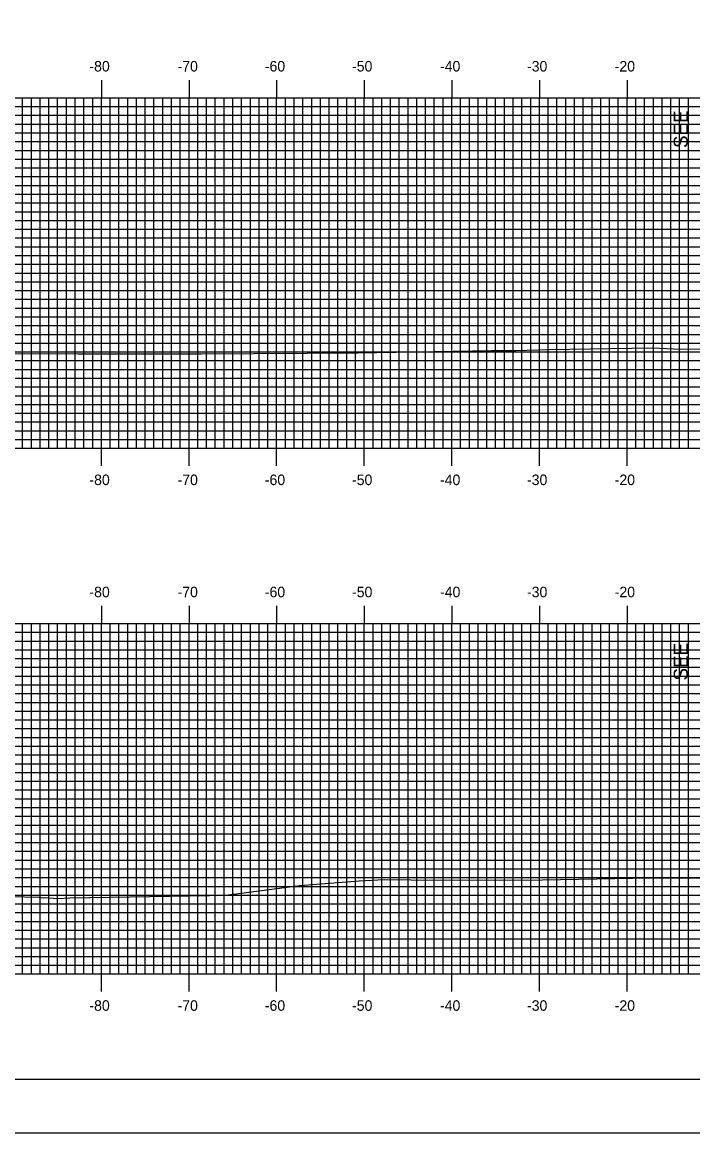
# Model space of a CAD drawing. Extents: x 2846 to 3190, y -1658 to -1438.
# Drawn here: x 2923.2 to 2999.7, y -1657.7 to -1531 of the extents above; entities that cross this region are included whole.
import ezdxf

# ---------------------------------------------------------------- set-up
doc = ezdxf.new("R2010")
doc.units = 0
for name, color, linetype in [('ANNOTATION', 7, 'Continuous'), ('BORDER', 7, 'Continuous'), ('H_V ANNOTATION', 7, 'Continuous'), ('MAJOR', 7, 'Continuous'), ('MINOR', 7, 'Continuous'), ('PLOT BOUNDARY', 7, 'Continuous'), ('S_Roadway_Centerline', 7, 'Continuous')]:
    doc.layers.add(name, color=color, linetype=linetype)

msp = doc.modelspace()

# ---------------------------------------------------------------- linework, layer by layer
at = {"layer": 'BORDER'}
msp.add_lwpolyline([(2862.61, -1651.6), (3182.61, -1651.6), (3182.61, -1441.6), (2862.61, -1441.6)], close=True, dxfattribs=at)
at = {"layer": 'MAJOR'}
for p, q in [((2932.21, -1537.6), (2932.21, -1539.6)), ((2942.21, -1537.6), (2942.21, -1539.6)), ((2952.21, -1537.6), (2952.21, -1539.6)), ((2962.21, -1537.6), (2962.21, -1539.6)), ((2972.21, -1537.6), (2972.21, -1539.6)), ((2982.21, -1537.6), (2982.21, -1539.6)), ((2992.21, -1537.6), (2992.21, -1539.6)), ((2872.21, -1539.6), (3152.21, -1539.6)), ((2872.21, -1539.6), (3152.21, -1539.6)), ((2932.21, -1579.6), (2932.21, -1539.6)), ((2942.21, -1579.6), (2942.21, -1539.6)), ((2952.21, -1579.6), (2952.21, -1539.6)), ((2962.21, -1579.6), (2962.21, -1539.6)), ((2972.21, -1579.6), (2972.21, -1539.6)), ((2982.21, -1579.6), (2982.21, -1539.6)), ((2992.21, -1579.6), (2992.21, -1539.6)), ((2872.21, -1544.6), (3152.21, -1544.6)), ((2872.21, -1549.6), (3152.21, -1549.6)), ((2872.21, -1554.6), (3152.21, -1554.6)), ((2872.21, -1559.6), (3152.21, -1559.6)), ((2872.21, -1564.6), (3152.21, -1564.6)), ((2872.21, -1569.6), (3152.21, -1569.6)), ((2872.21, -1574.6), (3152.21, -1574.6)), ((2872.21, -1579.6), (3152.21, -1579.6)), ((2872.21, -1579.6), (3152.21, -1579.6)), ((2932.21, -1581.61), (2932.21, -1579.6)), ((2942.21, -1581.61), (2942.21, -1579.6)), ((2952.21, -1581.61), (2952.21, -1579.6)), ((2962.21, -1581.61), (2962.21, -1579.6)), ((2972.21, -1581.61), (2972.21, -1579.6)), ((2982.21, -1581.61), (2982.21, -1579.6)), ((2992.21, -1581.61), (2992.21, -1579.6)), ((2932.21, -1597.6), (2932.21, -1599.6)), ((2942.21, -1597.6), (2942.21, -1599.6)), ((2952.21, -1597.6), (2952.21, -1599.6)), ((2962.21, -1597.6), (2962.21, -1599.6)), ((2972.21, -1597.6), (2972.21, -1599.6)), ((2982.21, -1597.6), (2982.21, -1599.6)), ((2992.21, -1597.6), (2992.21, -1599.6)), ((2872.21, -1599.6), (3152.21, -1599.6)), ((2872.21, -1599.6), (3152.21, -1599.6)), ((2932.21, -1639.6), (2932.21, -1599.6)), ((2942.21, -1639.6), (2942.21, -1599.6)), ((2952.21, -1639.6), (2952.21, -1599.6)), ((2962.21, -1639.6), (2962.21, -1599.6)), ((2972.21, -1639.6), (2972.21, -1599.6)), ((2982.21, -1639.6), (2982.21, -1599.6)), ((2992.21, -1639.6), (2992.21, -1599.6)), ((2872.21, -1604.6), (3152.21, -1604.6)), ((2872.21, -1609.6), (3152.21, -1609.6)), ((2872.21, -1614.6), (3152.21, -1614.6)), ((2872.21, -1619.6), (3152.21, -1619.6)), ((2872.21, -1624.6), (3152.21, -1624.6)), ((2872.21, -1629.6), (3152.21, -1629.6)), ((2872.21, -1634.6), (3152.21, -1634.6)), ((2872.21, -1639.6), (3152.21, -1639.6)), ((2872.21, -1639.6), (3152.21, -1639.6)), ((2932.21, -1641.61), (2932.21, -1639.6)), ((2942.21, -1641.61), (2942.21, -1639.6)), ((2952.21, -1641.61), (2952.21, -1639.6)), ((2962.21, -1641.61), (2962.21, -1639.6)), ((2972.21, -1641.61), (2972.21, -1639.6)), ((2982.21, -1641.61), (2982.21, -1639.6)), ((2992.21, -1641.61), (2992.21, -1639.6))]:
    msp.add_line(p, q, dxfattribs=at)
at = {"layer": 'MINOR'}
for p, q in [((2923.21, -1579.6), (2923.21, -1539.6)), ((2924.21, -1579.6), (2924.21, -1539.6)), ((2925.21, -1579.6), (2925.21, -1539.6)), ((2926.21, -1579.6), (2926.21, -1539.6)), ((2927.21, -1579.6), (2927.21, -1539.6)), ((2928.21, -1579.6), (2928.21, -1539.6)), ((2929.21, -1579.6), (2929.21, -1539.6)), ((2930.21, -1579.6), (2930.21, -1539.6)), ((2931.21, -1579.6), (2931.21, -1539.6)), ((2933.21, -1579.6), (2933.21, -1539.6)), ((2934.21, -1579.6), (2934.21, -1539.6)), ((2935.21, -1579.6), (2935.21, -1539.6)), ((2936.21, -1579.6), (2936.21, -1539.6)), ((2937.21, -1579.6), (2937.21, -1539.6)), ((2938.21, -1579.6), (2938.21, -1539.6)), ((2939.21, -1579.6), (2939.21, -1539.6)), ((2940.21, -1579.6), (2940.21, -1539.6)), ((2941.21, -1579.6), (2941.21, -1539.6)), ((2943.21, -1579.6), (2943.21, -1539.6)), ((2944.21, -1579.6), (2944.21, -1539.6)), ((2945.21, -1579.6), (2945.21, -1539.6)), ((2946.21, -1579.6), (2946.21, -1539.6)), ((2947.21, -1579.6), (2947.21, -1539.6)), ((2948.21, -1579.6), (2948.21, -1539.6)), ((2949.21, -1579.6), (2949.21, -1539.6)), ((2950.21, -1579.6), (2950.21, -1539.6)), ((2951.21, -1579.6), (2951.21, -1539.6)), ((2953.21, -1579.6), (2953.21, -1539.6)), ((2954.21, -1579.6), (2954.21, -1539.6)), ((2955.21, -1579.6), (2955.21, -1539.6)), ((2956.21, -1579.6), (2956.21, -1539.6)), ((2957.21, -1579.6), (2957.21, -1539.6)), ((2958.21, -1579.6), (2958.21, -1539.6)), ((2959.21, -1579.6), (2959.21, -1539.6)), ((2960.21, -1579.6), (2960.21, -1539.6)), ((2961.21, -1579.6), (2961.21, -1539.6)), ((2963.21, -1579.6), (2963.21, -1539.6)), ((2964.21, -1579.6), (2964.21, -1539.6)), ((2965.21, -1579.6), (2965.21, -1539.6)), ((2966.21, -1579.6), (2966.21, -1539.6)), ((2967.21, -1579.6), (2967.21, -1539.6)), ((2968.21, -1579.6), (2968.21, -1539.6)), ((2969.21, -1579.6), (2969.21, -1539.6)), ((2970.21, -1579.6), (2970.21, -1539.6)), ((2971.21, -1579.6), (2971.21, -1539.6)), ((2973.21, -1579.6), (2973.21, -1539.6)), ((2974.21, -1579.6), (2974.21, -1539.6)), ((2975.21, -1579.6), (2975.21, -1539.6)), ((2976.21, -1579.6), (2976.21, -1539.6)), ((2977.21, -1579.6), (2977.21, -1539.6)), ((2978.21, -1579.6), (2978.21, -1539.6)), ((2979.21, -1579.6), (2979.21, -1539.6)), ((2980.21, -1579.6), (2980.21, -1539.6)), ((2981.21, -1579.6), (2981.21, -1539.6)), ((2983.21, -1579.6), (2983.21, -1539.6)), ((2984.21, -1579.6), (2984.21, -1539.6)), ((2985.21, -1579.6), (2985.21, -1539.6)), ((2986.21, -1579.6), (2986.21, -1539.6)), ((2987.21, -1579.6), (2987.21, -1539.6)), ((2988.21, -1579.6), (2988.21, -1539.6)), ((2989.21, -1579.6), (2989.21, -1539.6)), ((2990.21, -1579.6), (2990.21, -1539.6)), ((2991.21, -1579.6), (2991.21, -1539.6)), ((2993.21, -1579.6), (2993.21, -1539.6)), ((2994.21, -1579.6), (2994.21, -1539.6)), ((2995.21, -1579.6), (2995.21, -1539.6)), ((2996.21, -1579.6), (2996.21, -1539.6)), ((2997.21, -1579.6), (2997.21, -1539.6)), ((2998.21, -1579.6), (2998.21, -1539.6)), ((2999.21, -1579.6), (2999.21, -1539.6)), ((2872.21, -1540.6), (3152.21, -1540.6)), ((2872.21, -1541.6), (3152.21, -1541.6)), ((2872.21, -1542.6), (3152.21, -1542.6)), ((2872.21, -1543.6), (3152.21, -1543.6)), ((2872.21, -1545.6), (3152.21, -1545.6)), ((2872.21, -1546.6), (3152.21, -1546.6)), ((2872.21, -1547.6), (3152.21, -1547.6)), ((2872.21, -1548.6), (3152.21, -1548.6)), ((2872.21, -1550.6), (3152.21, -1550.6)), ((2872.21, -1551.6), (3152.21, -1551.6)), ((2872.21, -1552.6), (3152.21, -1552.6)), ((2872.21, -1553.6), (3152.21, -1553.6)), ((2872.21, -1555.6), (3152.21, -1555.6)), ((2872.21, -1556.6), (3152.21, -1556.6)), ((2872.21, -1557.6), (3152.21, -1557.6)), ((2872.21, -1558.6), (3152.21, -1558.6)), ((2872.21, -1560.6), (3152.21, -1560.6)), ((2872.21, -1561.6), (3152.21, -1561.6)), ((2872.21, -1562.6), (3152.21, -1562.6)), ((2872.21, -1563.6), (3152.21, -1563.6)), ((2872.21, -1565.6), (3152.21, -1565.6)), ((2872.21, -1566.6), (3152.21, -1566.6)), ((2872.21, -1567.6), (3152.21, -1567.6)), ((2872.21, -1568.6), (3152.21, -1568.6)), ((2872.21, -1570.6), (3152.21, -1570.6)), ((2872.21, -1571.6), (3152.21, -1571.6)), ((2872.21, -1572.6), (3152.21, -1572.6)), ((2872.21, -1573.6), (3152.21, -1573.6)), ((2872.21, -1575.6), (3152.21, -1575.6)), ((2872.21, -1576.6), (3152.21, -1576.6)), ((2872.21, -1577.6), (3152.21, -1577.6)), ((2872.21, -1578.6), (3152.21, -1578.6)), ((2872.21, -1600.6), (3152.21, -1600.6)), ((2923.21, -1639.6), (2923.21, -1599.6)), ((2924.21, -1639.6), (2924.21, -1599.6)), ((2925.21, -1639.6), (2925.21, -1599.6)), ((2926.21, -1639.6), (2926.21, -1599.6)), ((2927.21, -1639.6), (2927.21, -1599.6)), ((2928.21, -1639.6), (2928.21, -1599.6)), ((2929.21, -1639.6), (2929.21, -1599.6)), ((2930.21, -1639.6), (2930.21, -1599.6)), ((2931.21, -1639.6), (2931.21, -1599.6)), ((2933.21, -1639.6), (2933.21, -1599.6)), ((2934.21, -1639.6), (2934.21, -1599.6)), ((2935.21, -1639.6), (2935.21, -1599.6)), ((2936.21, -1639.6), (2936.21, -1599.6)), ((2937.21, -1639.6), (2937.21, -1599.6)), ((2938.21, -1639.6), (2938.21, -1599.6)), ((2939.21, -1639.6), (2939.21, -1599.6)), ((2940.21, -1639.6), (2940.21, -1599.6)), ((2941.21, -1639.6), (2941.21, -1599.6)), ((2943.21, -1639.6), (2943.21, -1599.6)), ((2944.21, -1639.6), (2944.21, -1599.6)), ((2945.21, -1639.6), (2945.21, -1599.6)), ((2946.21, -1639.6), (2946.21, -1599.6)), ((2947.21, -1639.6), (2947.21, -1599.6)), ((2948.21, -1639.6), (2948.21, -1599.6)), ((2949.21, -1639.6), (2949.21, -1599.6)), ((2950.21, -1639.6), (2950.21, -1599.6)), ((2951.21, -1639.6), (2951.21, -1599.6)), ((2953.21, -1639.6), (2953.21, -1599.6)), ((2954.21, -1639.6), (2954.21, -1599.6)), ((2955.21, -1639.6), (2955.21, -1599.6)), ((2956.21, -1639.6), (2956.21, -1599.6)), ((2957.21, -1639.6), (2957.21, -1599.6)), ((2958.21, -1639.6), (2958.21, -1599.6)), ((2959.21, -1639.6), (2959.21, -1599.6)), ((2960.21, -1639.6), (2960.21, -1599.6)), ((2961.21, -1639.6), (2961.21, -1599.6)), ((2963.21, -1639.6), (2963.21, -1599.6)), ((2964.21, -1639.6), (2964.21, -1599.6)), ((2965.21, -1639.6), (2965.21, -1599.6)), ((2966.21, -1639.6), (2966.21, -1599.6)), ((2967.21, -1639.6), (2967.21, -1599.6)), ((2968.21, -1639.6), (2968.21, -1599.6)), ((2969.21, -1639.6), (2969.21, -1599.6)), ((2970.21, -1639.6), (2970.21, -1599.6)), ((2971.21, -1639.6), (2971.21, -1599.6)), ((2973.21, -1639.6), (2973.21, -1599.6)), ((2974.21, -1639.6), (2974.21, -1599.6)), ((2975.21, -1639.6), (2975.21, -1599.6)), ((2976.21, -1639.6), (2976.21, -1599.6)), ((2977.21, -1639.6), (2977.21, -1599.6)), ((2978.21, -1639.6), (2978.21, -1599.6)), ((2979.21, -1639.6), (2979.21, -1599.6)), ((2980.21, -1639.6), (2980.21, -1599.6)), ((2981.21, -1639.6), (2981.21, -1599.6)), ((2983.21, -1639.6), (2983.21, -1599.6)), ((2984.21, -1639.6), (2984.21, -1599.6)), ((2985.21, -1639.6), (2985.21, -1599.6)), ((2986.21, -1639.6), (2986.21, -1599.6)), ((2987.21, -1639.6), (2987.21, -1599.6)), ((2988.21, -1639.6), (2988.21, -1599.6)), ((2989.21, -1639.6), (2989.21, -1599.6)), ((2990.21, -1639.6), (2990.21, -1599.6)), ((2991.21, -1639.6), (2991.21, -1599.6)), ((2993.21, -1639.6), (2993.21, -1599.6)), ((2994.21, -1639.6), (2994.21, -1599.6)), ((2995.21, -1639.6), (2995.21, -1599.6)), ((2996.21, -1639.6), (2996.21, -1599.6)), ((2997.21, -1639.6), (2997.21, -1599.6)), ((2998.21, -1639.6), (2998.21, -1599.6)), ((2999.21, -1639.6), (2999.21, -1599.6)), ((2872.21, -1601.6), (3152.21, -1601.6)), ((2872.21, -1602.6), (3152.21, -1602.6)), ((2872.21, -1603.6), (3152.21, -1603.6)), ((2872.21, -1605.6), (3152.21, -1605.6)), ((2872.21, -1606.6), (3152.21, -1606.6)), ((2872.21, -1607.6), (3152.21, -1607.6)), ((2872.21, -1608.6), (3152.21, -1608.6)), ((2872.21, -1610.6), (3152.21, -1610.6)), ((2872.21, -1611.6), (3152.21, -1611.6)), ((2872.21, -1612.6), (3152.21, -1612.6)), ((2872.21, -1613.6), (3152.21, -1613.6)), ((2872.21, -1615.6), (3152.21, -1615.6)), ((2872.21, -1616.6), (3152.21, -1616.6)), ((2872.21, -1617.6), (3152.21, -1617.6)), ((2872.21, -1618.6), (3152.21, -1618.6)), ((2872.21, -1620.6), (3152.21, -1620.6)), ((2872.21, -1621.6), (3152.21, -1621.6)), ((2872.21, -1622.6), (3152.21, -1622.6)), ((2872.21, -1623.6), (3152.21, -1623.6)), ((2872.21, -1625.6), (3152.21, -1625.6)), ((2872.21, -1626.6), (3152.21, -1626.6)), ((2872.21, -1627.6), (3152.21, -1627.6)), ((2872.21, -1628.6), (3152.21, -1628.6)), ((2872.21, -1630.6), (3152.21, -1630.6)), ((2872.21, -1631.6), (3152.21, -1631.6)), ((2872.21, -1632.6), (3152.21, -1632.6)), ((2872.21, -1633.6), (3152.21, -1633.6)), ((2872.21, -1635.6), (3152.21, -1635.6)), ((2872.21, -1636.6), (3152.21, -1636.6)), ((2872.21, -1637.6), (3152.21, -1637.6)), ((2872.21, -1638.6), (3152.21, -1638.6))]:
    msp.add_line(p, q, dxfattribs=at)
at = {"layer": 'PLOT BOUNDARY'}
msp.add_lwpolyline([(2846.43, -1657.72), (3186.43, -1657.72), (3186.43, -1437.72), (2846.43, -1437.72)], close=True, dxfattribs=at)
at = {"layer": 'S_Roadway_Centerline'}
for points in [[(2872.21, -1568.96), (2876.43, -1569.03), (2887.71, -1568.78), (2892.45, -1569.04), (2907.03, -1568.85), (2913.06, -1568.81), (2923.46, -1568.8), (2929.56, -1568.81), (2943.58, -1568.84), (2955.7, -1568.75), (2961.47, -1568.7), (2976.73, -1568.46), (2979.51, -1568.46), (2983.3, -1568.34), (2995.08, -1568.13), (2998.34, -1568.28), (3003.1, -1568.25)], [(2921.74, -1630.76), (2925.05, -1630.84), (2925.59, -1630.89), (2925.84, -1630.88), (2927.18, -1630.98), (2928.6, -1630.91), (2944.56, -1630.65), (2946.42, -1630.6), (2954.87, -1629.5), (2961.63, -1628.98), (2964.5, -1628.83), (2970.62, -1628.9), (2982.57, -1628.86), (2992.88, -1628.67), (3002.45, -1628.61)]]:
    msp.add_lwpolyline(points, dxfattribs=at)

# ---------------------------------------------------------------- texts
at = {"layer": 'ANNOTATION'}
for p in [(2999.14, -1545.33), (2999.14, -1606.1)]:
    msp.add_text('SEE', height=1.6, rotation=90, dxfattribs=at).set_placement(p)
at = {"layer": 'H_V ANNOTATION'}
for s, p in [('-80', (2930.84, -1536.6)), ('-70', (2940.9, -1536.6)), ('-60', (2950.86, -1536.6)), ('-50', (2960.82, -1536.6)), ('-40', (2970.86, -1536.6)), ('-30', (2980.79, -1536.6)), ('-20', (2990.8, -1536.6)), ('-80', (2930.84, -1583.8)), ('-70', (2940.9, -1583.8)), ('-60', (2950.86, -1583.8)), ('-50', (2960.82, -1583.8)), ('-40', (2970.86, -1583.8)), ('-30', (2980.79, -1583.8)), ('-20', (2990.8, -1583.8)), ('-80', (2930.84, -1596.6)), ('-70', (2940.9, -1596.6)), ('-60', (2950.86, -1596.6)), ('-50', (2960.82, -1596.6)), ('-40', (2970.86, -1596.6)), ('-30', (2980.79, -1596.6)), ('-20', (2990.8, -1596.6)), ('-80', (2930.84, -1643.8)), ('-70', (2940.9, -1643.8)), ('-60', (2950.86, -1643.8)), ('-50', (2960.82, -1643.8)), ('-40', (2970.86, -1643.8)), ('-30', (2980.79, -1643.8)), ('-20', (2990.8, -1643.8))]:
    msp.add_text(s, height=1.2, dxfattribs=at).set_placement(p)

doc.saveas('drawing.dxf')
